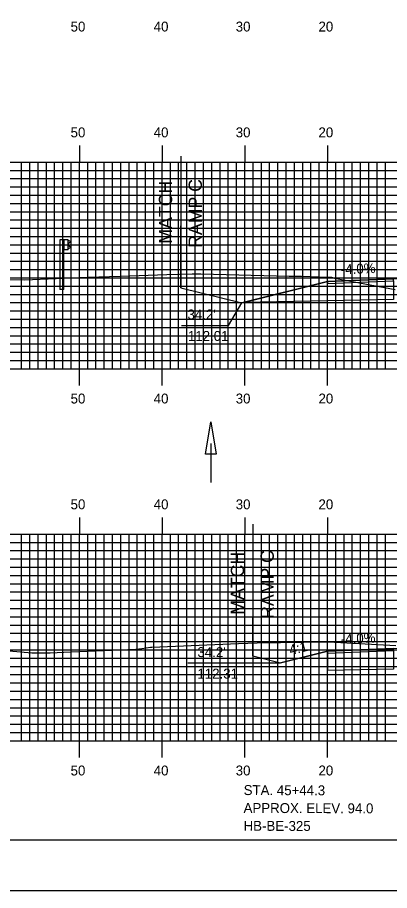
# Model space of a CAD drawing. Extents: x 1754314 to 1754654, y 442591 to 442811.
# Drawn here: x 1754422.5 to 1754467.5, y 442590.5 to 442696.2 of the extents above; entities that cross this region are included whole.
import ezdxf

# ---------------------------------------------------------------- set-up
doc = ezdxf.new("R2010")
doc.units = 0
for name, color, linetype in [('ANNOTATION', 7, 'Continuous'), ('BORDER', 7, 'Continuous'), ('BORING - NO REFUSAL', 7, 'Continuous'), ('D_Drainage_Ditch_Line', 7, 'Continuous'), ('D_Roadway_Centerline', 7, 'Continuous'), ('D_Roadway_Edge_Shoulder', 7, 'Continuous'), ('D_Roadway_SlopeLines', 7, 'Continuous'), ('D_Roadway_SubGrade', 7, 'Continuous'), ('H_V ANNOTATION', 7, 'Continuous'), ('M_Guardrail', 7, 'Continuous'), ('M_Roadway_Centerline', 7, 'Continuous'), ('MAJOR', 7, 'Continuous'), ('MINOR', 7, 'Continuous'), ('PDRAIN', 7, 'Continuous'), ('PLOT BOUNDARY', 7, 'Continuous'), ('S_Roadway_Centerline', 7, 'Continuous')]:
    doc.layers.add(name, color=color, linetype=linetype)

msp = doc.modelspace()

# ---------------------------------------------------------------- linework, layer by layer
at = {"layer": 'ANNOTATION'}
msp.add_lwpolyline([(1754442.34, 442658.91), (1754448.03, 442658.91), (1754449.66, 442661.64)], dxfattribs=at)
at = {"layer": 'BORDER'}
msp.add_lwpolyline([(1754330.4, 442596.67), (1754650.4, 442596.67), (1754650.4, 442806.67), (1754330.4, 442806.67)], close=True, dxfattribs=at)
at = {"layer": 'D_Drainage_Ditch_Line'}
msp.add_line((1754445.88, 442644.63), (1754445.88, 442639.93), dxfattribs=at)
msp.add_lwpolyline([(1754446.54, 442643.32), (1754445.23, 442643.32), (1754445.88, 442647.25)], close=True, dxfattribs=at)
at = {"layer": 'D_Roadway_Centerline'}
for points in [[(1754449.66, 442661.64), (1754449.83, 442661.68), (1754460, 442664.22), (1754468, 442664.54), (1754480, 442664.78), (1754492, 442664.54), (1754493.2, 442664.52), (1754501.2, 442664.2), (1754511.38, 442661.65), (1754515.38, 442660.65), (1754522.28, 442664.11), (1754523.28, 442664.54), (1754524.28, 442664.84), (1754525.28, 442665.01), (1754526.28, 442665.04)], [(1754442.25, 442663.45), (1754449.66, 442661.64)], [(1754454.33, 442618.1), (1754460, 442619.52), (1754468, 442619.84), (1754480, 442620.08), (1754492, 442619.84), (1754500, 442619.52), (1754510.18, 442616.97), (1754514.18, 442615.97), (1754521.9, 442619.83), (1754522.9, 442620.27), (1754523.9, 442620.58), (1754524.9, 442620.75), (1754525.9, 442620.8)]]:
    msp.add_lwpolyline(points, dxfattribs=at)
at = {"layer": 'D_Roadway_Edge_Shoulder'}
for points in [[(1754468, 442664.54), (1754460, 442664.22), (1754460, 442663.97), (1754468, 442664.29)], [(1754468, 442619.84), (1754460, 442619.52), (1754460, 442619.27), (1754468, 442619.59)]]:
    msp.add_lwpolyline(points, close=True, dxfattribs=at)
at = {"layer": 'D_Roadway_SlopeLines'}
for p, q in [((1754442.25, 442663.45), (1754442.25, 442670.97)), ((1754450.96, 442618.94), (1754450.96, 442623.58)), ((1754460, 442619.52), (1754460, 442617.18)), ((1754450.96, 442618.94), (1754454.33, 442618.1))]:
    msp.add_line(p, q, dxfattribs=at)
for points in [[(1754460, 442664.22), (1754449.66, 442661.64)], [(1754460, 442619.52), (1754454.34, 442618.1)]]:
    msp.add_lwpolyline(points, dxfattribs=at)
at = {"layer": 'D_Roadway_SubGrade'}
for p, q in [((1754442.25, 442679.4), (1754442.25, 442663.45)), ((1754450.96, 442634.89), (1754450.96, 442618.94))]:
    msp.add_line(p, q, dxfattribs=at)
for points in [[(1754460, 442663.97), (1754468, 442664.29), (1754468, 442663.88), (1754468, 442662.04), (1754449.83, 442661.68), (1754460, 442664.22)], [(1754460, 442619.27), (1754468, 442619.59), (1754468, 442619.17), (1754468, 442617.34), (1754460, 442617.18), (1754460, 442619.52)]]:
    msp.add_lwpolyline(points, close=True, dxfattribs=at)
at = {"layer": 'M_Guardrail'}
for p, q in [((1754427.64, 442669.28), (1754427.64, 442663.28)), ((1754428.13, 442669.28), (1754427.64, 442669.28)), ((1754428.62, 442669.28), (1754428.13, 442669.28)), ((1754428.13, 442669.28), (1754428.13, 442668.12)), ((1754428.62, 442668.12), (1754428.62, 442669.28)), ((1754428.62, 442669.21), (1754428.71, 442669.2)), ((1754428.72, 442669.19), (1754428.87, 442669.09)), ((1754428.13, 442663.28), (1754428.13, 442668.12)), ((1754428.13, 442668.12), (1754428.62, 442668.12)), ((1754428.71, 442668.2), (1754428.62, 442668.19)), ((1754428.64, 442668.75), (1754428.64, 442668.65)), ((1754428.87, 442668.95), (1754428.67, 442668.81)), ((1754428.67, 442668.59), (1754428.87, 442668.45)), ((1754428.87, 442668.31), (1754428.72, 442668.21)), ((1754428.13, 442663.28), (1754427.64, 442663.28))]:
    msp.add_line(p, q, dxfattribs=at)
for centre, major_axis, start_param, end_param in [((1754428.7, 442669.15), (0.0417, 0), 0.959931, 1.396263), ((1754428.82, 442669.02), (0.0877, 0), 5.323254, 7.243116), ((1754428.72, 442668.75), (-0.0789, 0), 5.323254, 6.283185), ((1754428.72, 442668.65), (-0.0789, 0), 6.283185, 7.243116), ((1754428.7, 442668.24), (0.0417, 0), 4.886922, 5.323254), ((1754428.82, 442668.38), (0.0877, 0), 5.323254, 7.243116)]:
    msp.add_ellipse(centre, major_axis=major_axis, ratio=0.995501, start_param=start_param, end_param=end_param, dxfattribs=at)
at = {"layer": 'MAJOR'}
for p, q in [((1754430, 442680.67), (1754430, 442678.67)), ((1754440, 442680.67), (1754440, 442678.67)), ((1754450, 442680.67), (1754450, 442678.67)), ((1754460, 442680.67), (1754460, 442678.67)), ((1754340, 442678.67), (1754620, 442678.67)), ((1754340, 442678.67), (1754620, 442678.67)), ((1754430, 442653.67), (1754430, 442678.67)), ((1754440, 442653.67), (1754440, 442678.67)), ((1754450, 442653.67), (1754450, 442678.67)), ((1754460, 442653.67), (1754460, 442678.67)), ((1754340, 442668.67), (1754620, 442668.67)), ((1754340, 442663.67), (1754620, 442663.67)), ((1754340, 442658.67), (1754620, 442658.67)), ((1754340, 442653.67), (1754620, 442653.67)), ((1754340, 442653.67), (1754620, 442653.67)), ((1754430, 442651.66), (1754430, 442653.67)), ((1754440, 442651.66), (1754440, 442653.67)), ((1754450, 442651.66), (1754450, 442653.67)), ((1754460, 442651.66), (1754460, 442653.67)), ((1754430, 442635.67), (1754430, 442633.67)), ((1754440, 442635.67), (1754440, 442633.67)), ((1754450, 442635.67), (1754450, 442633.67)), ((1754460, 442635.67), (1754460, 442633.67)), ((1754340, 442633.67), (1754620, 442633.67)), ((1754340, 442633.67), (1754620, 442633.67)), ((1754430, 442608.67), (1754430, 442633.67)), ((1754440, 442608.67), (1754440, 442633.67)), ((1754450, 442608.67), (1754450, 442633.67)), ((1754460, 442608.67), (1754460, 442633.67)), ((1754340, 442628.67), (1754620, 442628.67)), ((1754340, 442623.67), (1754620, 442623.67)), ((1754340, 442618.67), (1754620, 442618.67)), ((1754340, 442613.67), (1754620, 442613.67)), ((1754340, 442608.67), (1754620, 442608.67)), ((1754340, 442608.67), (1754620, 442608.67)), ((1754430, 442606.66), (1754430, 442608.67)), ((1754440, 442606.66), (1754440, 442608.67)), ((1754450, 442606.66), (1754450, 442608.67)), ((1754460, 442606.66), (1754460, 442608.67))]:
    msp.add_line(p, q, dxfattribs=at)
at = {"layer": 'MINOR'}
for p, q in [((1754423, 442653.67), (1754423, 442678.67)), ((1754424, 442653.67), (1754424, 442678.67)), ((1754425, 442653.67), (1754425, 442678.67)), ((1754426, 442653.67), (1754426, 442678.67)), ((1754427, 442653.67), (1754427, 442678.67)), ((1754428, 442653.67), (1754428, 442678.67)), ((1754429, 442653.67), (1754429, 442678.67)), ((1754431, 442653.67), (1754431, 442678.67)), ((1754432, 442653.67), (1754432, 442678.67)), ((1754433, 442653.67), (1754433, 442678.67)), ((1754434, 442653.67), (1754434, 442678.67)), ((1754435, 442653.67), (1754435, 442678.67)), ((1754436, 442653.67), (1754436, 442678.67)), ((1754437, 442653.67), (1754437, 442678.67)), ((1754438, 442653.67), (1754438, 442678.67)), ((1754439, 442653.67), (1754439, 442678.67)), ((1754441, 442653.67), (1754441, 442678.67)), ((1754442, 442653.67), (1754442, 442678.67)), ((1754443, 442653.67), (1754443, 442678.67)), ((1754444, 442653.67), (1754444, 442678.67)), ((1754445, 442653.67), (1754445, 442678.67)), ((1754446, 442653.67), (1754446, 442678.67)), ((1754447, 442653.67), (1754447, 442678.67)), ((1754448, 442653.67), (1754448, 442678.67)), ((1754449, 442653.67), (1754449, 442678.67)), ((1754451, 442653.67), (1754451, 442678.67)), ((1754452, 442653.67), (1754452, 442678.67)), ((1754453, 442653.67), (1754453, 442678.67)), ((1754454, 442653.67), (1754454, 442678.67)), ((1754455, 442653.67), (1754455, 442678.67)), ((1754456, 442653.67), (1754456, 442678.67)), ((1754457, 442653.67), (1754457, 442678.67)), ((1754458, 442653.67), (1754458, 442678.67)), ((1754459, 442653.67), (1754459, 442678.67)), ((1754461, 442653.67), (1754461, 442678.67)), ((1754462, 442653.67), (1754462, 442678.67)), ((1754463, 442653.67), (1754463, 442678.67)), ((1754464, 442653.67), (1754464, 442678.67)), ((1754465, 442653.67), (1754465, 442678.67)), ((1754466, 442653.67), (1754466, 442678.67)), ((1754467, 442653.67), (1754467, 442678.67)), ((1754340, 442677.67), (1754620, 442677.67)), ((1754340, 442676.67), (1754620, 442676.67)), ((1754340, 442675.67), (1754620, 442675.67)), ((1754340, 442674.67), (1754620, 442674.67)), ((1754340, 442673.67), (1754620, 442673.67)), ((1754340, 442672.67), (1754620, 442672.67)), ((1754340, 442671.67), (1754620, 442671.67)), ((1754340, 442670.67), (1754620, 442670.67)), ((1754340, 442669.67), (1754620, 442669.67)), ((1754340, 442667.67), (1754620, 442667.67)), ((1754340, 442666.67), (1754620, 442666.67)), ((1754340, 442665.67), (1754620, 442665.67)), ((1754340, 442664.67), (1754620, 442664.67)), ((1754340, 442662.67), (1754620, 442662.67)), ((1754340, 442661.67), (1754620, 442661.67)), ((1754340, 442660.67), (1754620, 442660.67)), ((1754340, 442659.67), (1754620, 442659.67)), ((1754340, 442657.67), (1754620, 442657.67)), ((1754340, 442656.67), (1754620, 442656.67)), ((1754340, 442655.67), (1754620, 442655.67)), ((1754340, 442654.67), (1754620, 442654.67)), ((1754423, 442608.67), (1754423, 442633.67)), ((1754424, 442608.67), (1754424, 442633.67)), ((1754425, 442608.67), (1754425, 442633.67)), ((1754426, 442608.67), (1754426, 442633.67)), ((1754427, 442608.67), (1754427, 442633.67)), ((1754428, 442608.67), (1754428, 442633.67)), ((1754429, 442608.67), (1754429, 442633.67)), ((1754431, 442608.67), (1754431, 442633.67)), ((1754432, 442608.67), (1754432, 442633.67)), ((1754433, 442608.67), (1754433, 442633.67)), ((1754434, 442608.67), (1754434, 442633.67)), ((1754435, 442608.67), (1754435, 442633.67)), ((1754436, 442608.67), (1754436, 442633.67)), ((1754437, 442608.67), (1754437, 442633.67)), ((1754438, 442608.67), (1754438, 442633.67)), ((1754439, 442608.67), (1754439, 442633.67)), ((1754441, 442608.67), (1754441, 442633.67)), ((1754442, 442608.67), (1754442, 442633.67)), ((1754443, 442608.67), (1754443, 442633.67)), ((1754444, 442608.67), (1754444, 442633.67)), ((1754445, 442608.67), (1754445, 442633.67)), ((1754446, 442608.67), (1754446, 442633.67)), ((1754447, 442608.67), (1754447, 442633.67)), ((1754448, 442608.67), (1754448, 442633.67)), ((1754449, 442608.67), (1754449, 442633.67)), ((1754451, 442608.67), (1754451, 442633.67)), ((1754452, 442608.67), (1754452, 442633.67)), ((1754453, 442608.67), (1754453, 442633.67)), ((1754454, 442608.67), (1754454, 442633.67)), ((1754455, 442608.67), (1754455, 442633.67)), ((1754456, 442608.67), (1754456, 442633.67)), ((1754457, 442608.67), (1754457, 442633.67)), ((1754458, 442608.67), (1754458, 442633.67)), ((1754459, 442608.67), (1754459, 442633.67)), ((1754461, 442608.67), (1754461, 442633.67)), ((1754462, 442608.67), (1754462, 442633.67)), ((1754463, 442608.67), (1754463, 442633.67)), ((1754464, 442608.67), (1754464, 442633.67)), ((1754465, 442608.67), (1754465, 442633.67)), ((1754466, 442608.67), (1754466, 442633.67)), ((1754467, 442608.67), (1754467, 442633.67)), ((1754340, 442632.67), (1754620, 442632.67)), ((1754340, 442631.67), (1754620, 442631.67)), ((1754340, 442630.67), (1754620, 442630.67)), ((1754340, 442629.67), (1754620, 442629.67)), ((1754340, 442627.67), (1754620, 442627.67)), ((1754340, 442626.67), (1754620, 442626.67)), ((1754340, 442625.67), (1754620, 442625.67)), ((1754340, 442624.67), (1754620, 442624.67)), ((1754340, 442622.67), (1754620, 442622.67)), ((1754340, 442621.67), (1754620, 442621.67)), ((1754340, 442620.67), (1754620, 442620.67)), ((1754340, 442619.67), (1754620, 442619.67)), ((1754340, 442617.67), (1754620, 442617.67)), ((1754340, 442616.67), (1754620, 442616.67)), ((1754340, 442615.67), (1754620, 442615.67)), ((1754340, 442614.67), (1754620, 442614.67)), ((1754340, 442612.67), (1754620, 442612.67)), ((1754340, 442611.67), (1754620, 442611.67)), ((1754340, 442610.67), (1754620, 442610.67)), ((1754340, 442609.67), (1754620, 442609.67))]:
    msp.add_line(p, q, dxfattribs=at)
at = {"layer": 'PDRAIN'}
msp.add_line((1754443.11, 442618.1), (1754454.33, 442618.1), dxfattribs=at)
at = {"layer": 'PLOT BOUNDARY'}
msp.add_lwpolyline([(1754314.22, 442590.55), (1754654.22, 442590.55), (1754654.22, 442810.55), (1754314.22, 442810.55)], close=True, dxfattribs=at)
at = {"layer": 'S_Roadway_Centerline'}
for points in [[(1754414.64, 442664.54), (1754423.35, 442664.42), (1754431.03, 442664.75), (1754434.98, 442664.89), (1754440.56, 442665.06), (1754443.64, 442665.15), (1754444.7, 442665.14), (1754455.35, 442664.87), (1754456.86, 442664.86), (1754459.01, 442664.78), (1754460.49, 442664.76), (1754460.84, 442664.64), (1754468.2, 442663.25)], [(1754419.15, 442619.74), (1754424.23, 442619.32), (1754426.46, 442619.32), (1754428.94, 442619.43), (1754436.82, 442619.76), (1754437.56, 442619.83), (1754438.6, 442619.97), (1754438.67, 442619.97), (1754438.7, 442619.98), (1754438.75, 442619.98), (1754449.24, 442620.45), (1754451.5, 442620.52), (1754459.97, 442620.63), (1754460.14, 442620.63), (1754468.27, 442620.18)]]:
    msp.add_lwpolyline(points, dxfattribs=at)

# ---------------------------------------------------------------- texts
at = {"layer": 'ANNOTATION'}
for s, height, rotation, p in [('RAMP C', 1.6, 90, (1754444.81, 442668.3)), ('MATCH', 1.6, 90, (1754441.21, 442668.81)), ('-4.0%', 1.2, 2.2906, (1754461.64, 442665.09)), ('MATCH', 1.6, 90, (1754449.91, 442623.92)), ('RAMP C', 1.6, 90, (1754453.51, 442623.41)), ('-4.0%', 1.2, 2.2906, (1754461.64, 442620.38)), ('4:1', 1.2, 14.0381, (1754455.52, 442619.03))]:
    msp.add_text(s, height=height, rotation=rotation, dxfattribs=at).set_placement(p)
for s, p in [("34.2'", (1754443.07, 442659.64)), ('112.01', (1754443.12, 442657.04)), ("34.2'", (1754444.27, 442618.79)), ('112.31', (1754444.27, 442616.19))]:
    msp.add_text(s, height=1.2, dxfattribs=at).set_placement(p)
at = {"layer": 'BORING - NO REFUSAL'}
for s, p in [('STA. 45+44.3', (1754449.86, 442602.1)), ('APPROX. ELEV. 94.0', (1754449.85, 442599.94)), ('HB-BE-325', (1754449.85, 442597.78))]:
    msp.add_text(s, height=1.2, rotation=359.8142, dxfattribs=at).set_placement(p)
at = {"layer": 'H_V ANNOTATION'}
for s, p in [('50', (1754428.93, 442694.47)), ('40', (1754438.98, 442694.47)), ('30', (1754448.9, 442694.47)), ('20', (1754458.91, 442694.47)), ('50', (1754428.93, 442681.67)), ('40', (1754438.98, 442681.67)), ('30', (1754448.9, 442681.67)), ('20', (1754458.91, 442681.67)), ('50', (1754428.93, 442649.47)), ('40', (1754438.98, 442649.47)), ('30', (1754448.9, 442649.47)), ('20', (1754458.91, 442649.47)), ('50', (1754428.93, 442636.67)), ('40', (1754438.98, 442636.67)), ('30', (1754448.9, 442636.67)), ('20', (1754458.91, 442636.67)), ('50', (1754428.93, 442604.47)), ('40', (1754438.98, 442604.47)), ('30', (1754448.9, 442604.47)), ('20', (1754458.91, 442604.47))]:
    msp.add_text(s, height=1.2, dxfattribs=at).set_placement(p)
at = {"layer": 'M_Roadway_Centerline'}
for s, p in [('L', (1754443.63, 442665.14)), ('C', (1754443.64, 442665.15)), ('C', (1754451.5, 442620.52)), ('L', (1754451.49, 442620.52))]:
    msp.add_text(s, height=0.0146, dxfattribs=at).set_placement(p)

doc.saveas('drawing.dxf')
